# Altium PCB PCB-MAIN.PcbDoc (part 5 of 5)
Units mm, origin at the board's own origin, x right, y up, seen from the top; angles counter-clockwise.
Board outline 110 x 75 mm, 8 copper layers (F.Cu, In1.Cu, In2.Cu, In3.Cu, In4.Cu, In5.Cu, In6.Cu, B.Cu); 251 components, 185 nets, 1143 pads, 853 vias.
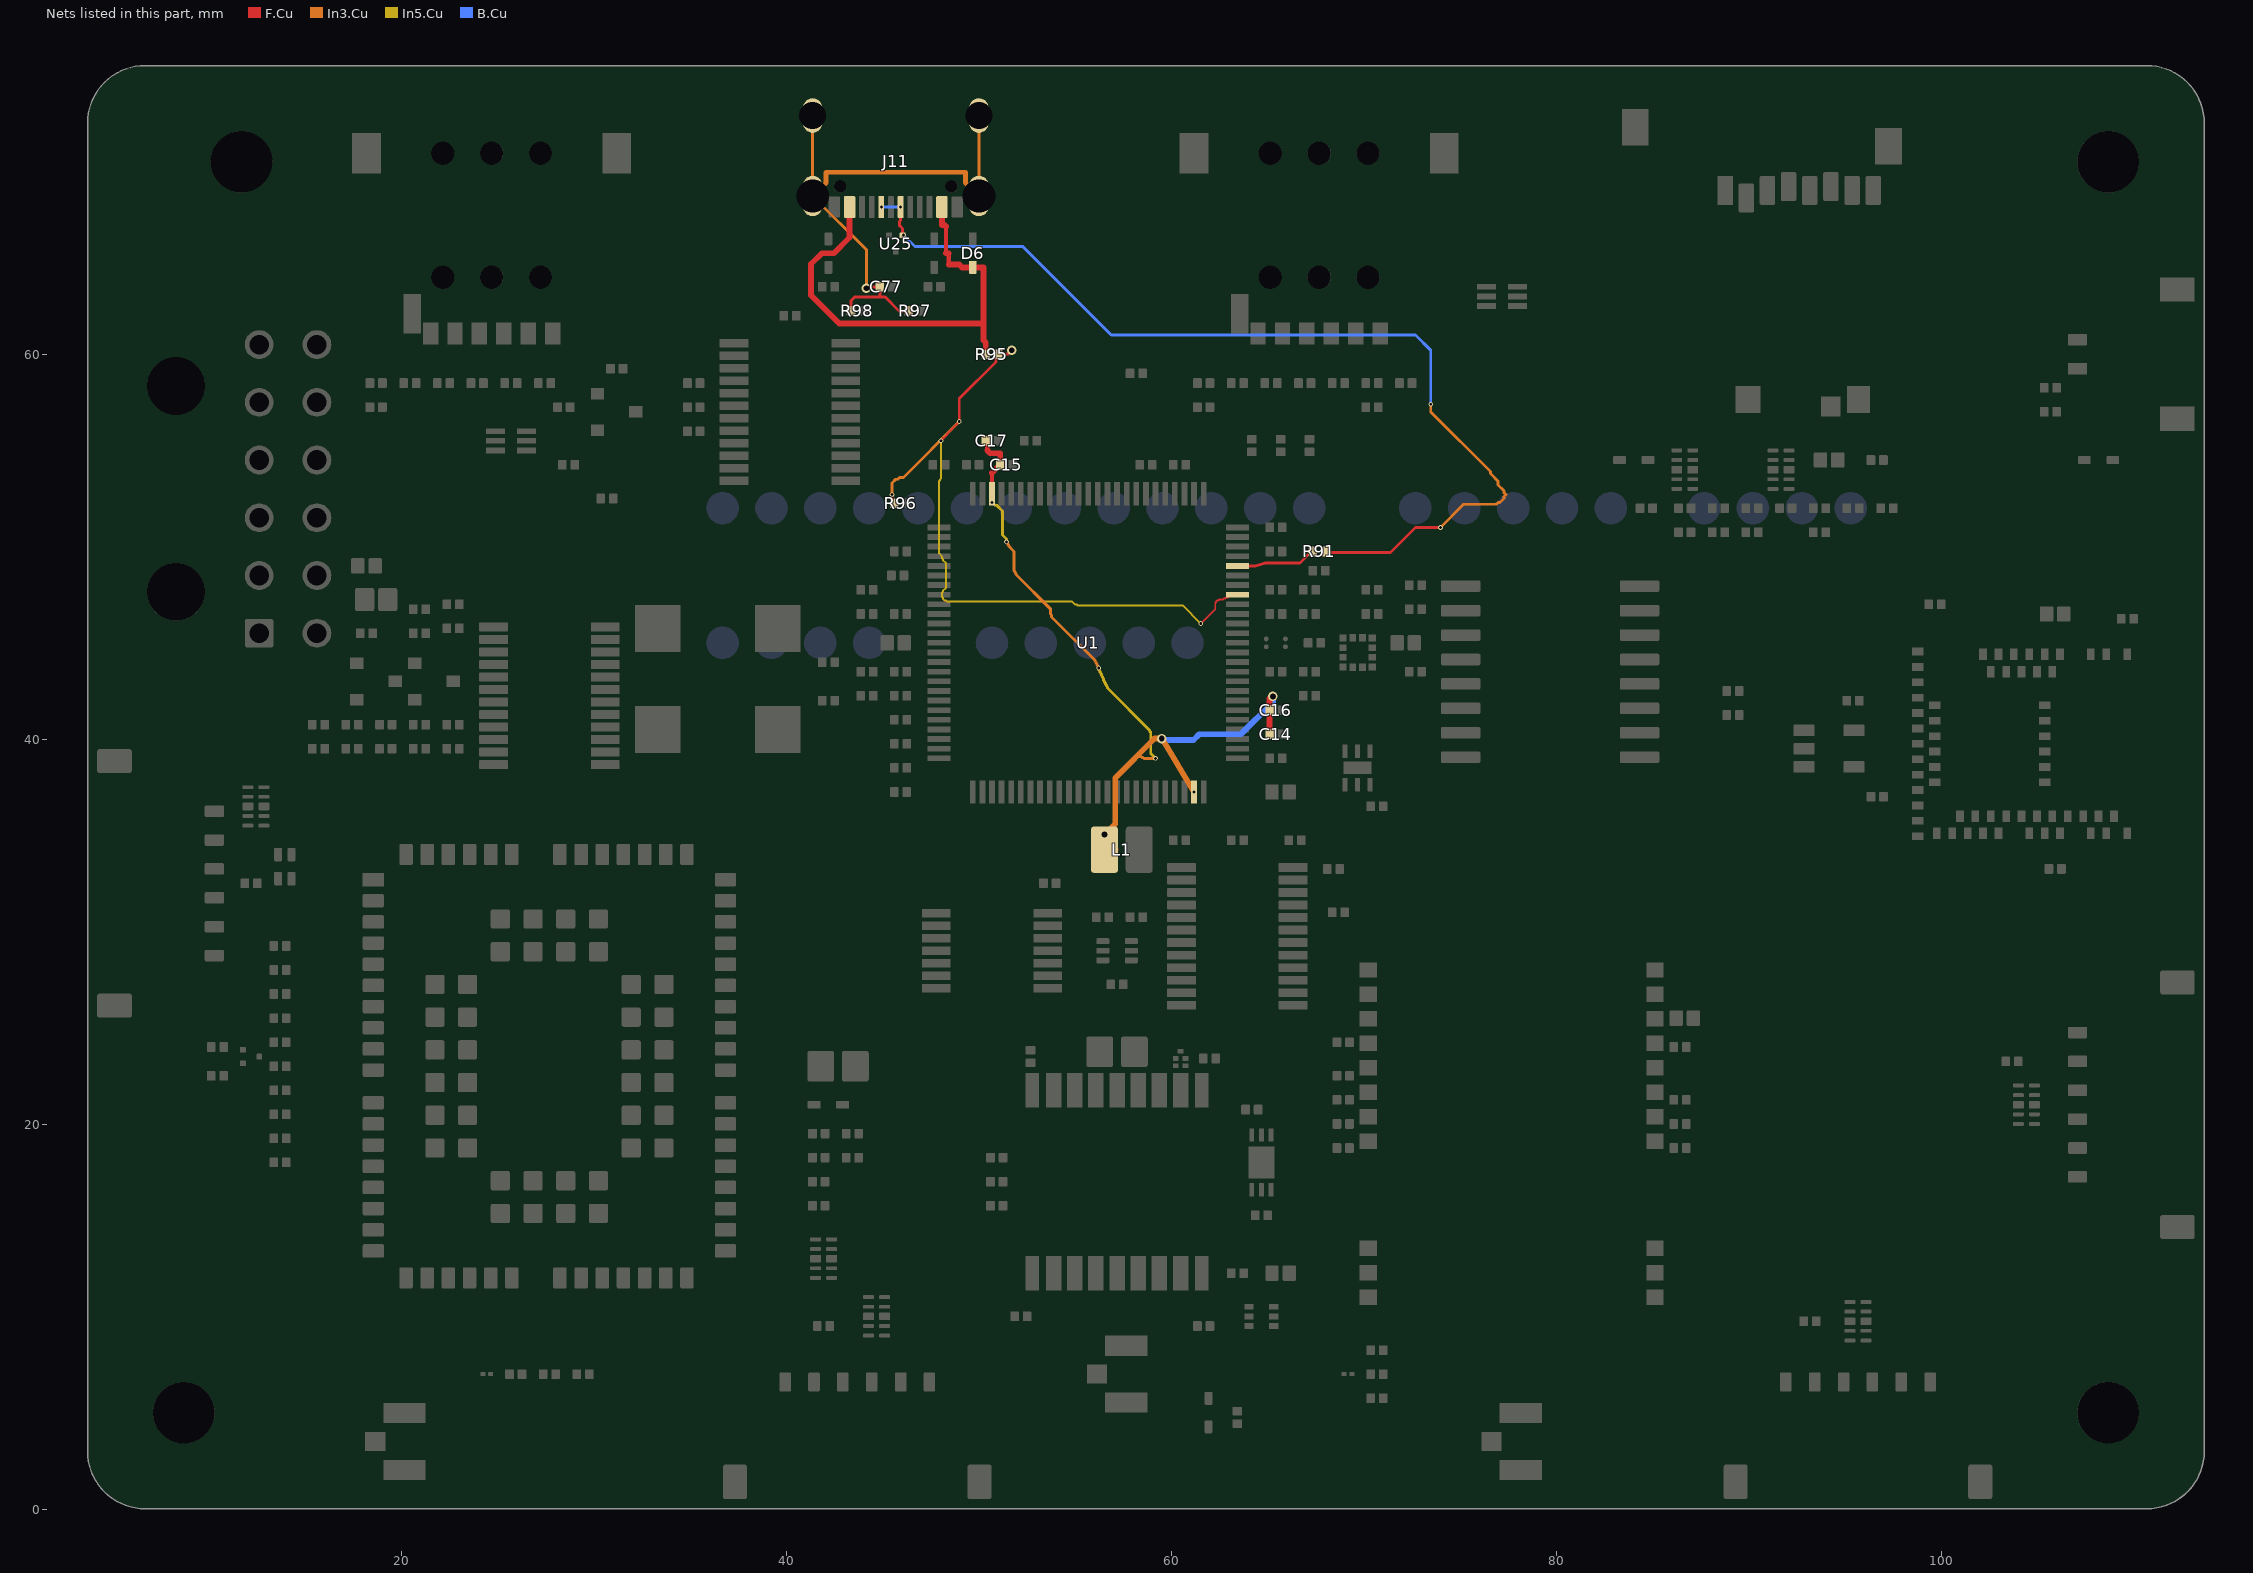
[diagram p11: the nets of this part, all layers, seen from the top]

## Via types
v1: diameter 0.5, hole 0.3, F.Cu to B.Cu, tented both sides, 579 vias
v2: diameter 0.25, hole 0.15, F.Cu to B.Cu, tented both sides, 274 vias

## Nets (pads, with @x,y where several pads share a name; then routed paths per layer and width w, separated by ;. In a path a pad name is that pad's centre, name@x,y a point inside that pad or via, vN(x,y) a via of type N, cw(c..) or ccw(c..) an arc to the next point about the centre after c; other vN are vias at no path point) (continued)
USB_DP_CONN: J11.A6 J11.B6 R91.2 U25.1 | length 52.2
  F.Cu w0.15: R91.2@68.085,49.725 71.385,49.725 72.685,51.025 v2(73.985,51.025)
  F.Cu w0.154: v2(45.935,67.67) 45.935,66.975 45.868,66.908 45.868,66.725 46.035,66.558 U25.1@46.035,66.2
  In3.Cu w0.15: v2(73.485,57.425) 73.485,57.025 76.585,53.925 76.585,53.825 76.985,53.425 76.985,53.225 77.285,52.925 77.285,52.825 77.385,52.725 77.285,52.625 77.285,52.525 77.085,52.325 76.985,52.325 76.885,52.225 75.185,52.225 v2(73.985,51.025)
  B.Cu w0.15: v2(46.085,66.225) 46.685,65.625 52.285,65.625 56.885,61.025 72.685,61.025 73.485,60.225 v2(73.485,57.425)
  B.Cu w0.154: v2(44.935,67.67) v2(45.935,67.67)
USB_DP_U1: R91.1 U1.71 | length 4.2
  F.Cu w0.154: U1.71@63.435,49.025 64.385,49.025 64.885,49.175 66.685,49.175 67.135,49.625 R91.1@67.36,49.775
USB_SHIELD: C77.1 J11.SHIELD R97.1 R98.1 | length 29.8
  F.Cu w0.15: R98.1@43.36,62.275 43.36,62.802 43.556,62.998 44.86,62.998 ; v1(44.159,63.449) 44.282,63.449 44.358,63.525 C77.1@44.86,63.525 44.86,62.998 ; R97.1@46.36,62.275 45.858,62.275 45.135,62.998 44.86,62.998
  In3.Cu w0.15: J11.SHIELD@41.365,72.425 J11.SHIELD@41.365,68.245 44.159,65.451 v1(44.159,63.449) ; J11.SHIELD@50.005,68.245 J11.SHIELD@50.005,72.425
  In3.Cu w0.25: J11.SHIELD@41.365,68.245 42.065,68.945 42.065,69.475 49.305,69.475 49.305,68.945 J11.SHIELD@50.005,68.245
USB_VBUS_CONN: D6.1 J11.A4 J11.A9 J11.B4 J11.B9 R95.1 | length 25.1
  F.Cu w0.225: 48.297,65.275 48.297,66.66 ; 48.435,64.683 48.435,65.275
  F.Cu w0.3: J11.B4@43.285,67.67 43.285,66.082 42.478,65.275 41.846,65.275 41.283,64.712 41.283,63.089 42.747,61.624 50.237,61.624 ; J11.B9@48.085,67.67 48.085,66.743 48.215,66.743 48.297,66.66 ; 48.297,65.275 48.435,65.275 ; 48.435,64.683 48.985,64.683 49.133,64.535 D6.1@49.685,64.535 50.237,64.535 50.237,61.624 ; R95.1@50.36,60.025 50.36,60.627 50.237,60.75 50.237,61.624
USB_VBUS_SENSE: R95.2 R96.1 U1.68 | length 37
  F.Cu w0.1: v2(48.035,55.525) 48.335,55.825 48.335,55.875 v2@48.935,56.475 ; v2(61.535,46.025) 62.285,46.775 62.285,47.075 62.335,47.125 62.335,47.175 62.385,47.225 62.435,47.225 62.485,47.275 62.685,47.275 62.735,47.325 62.785,47.325 62.835,47.375 62.935,47.375 U1.68@63.085,47.525
  F.Cu w0.15: v2(45.485,52.725) 45.485,52.525 45.585,52.425 R96.1@45.585,52.325 ; v2(48.985,56.525) 48.985,57.725 50.885,59.625 50.885,59.825 R95.2@50.985,59.925 ; R95.2@51.01,60.025 51.512,60.025 v1(51.712,60.225)
  In3.Cu w0.15: v2(45.485,52.725) 45.485,53.325 45.685,53.525 45.785,53.525 45.885,53.625 46.085,53.625 v2(48.985,56.525)
  In5.Cu w0.1: v2(48.035,55.525) 48.035,53.575 47.985,53.525 47.985,53.475 47.935,53.425 47.935,49.675 48.085,49.525 48.085,49.425 48.135,49.375 48.135,49.325 48.285,49.175 48.285,47.875 48.135,47.725 48.135,47.675 48.085,47.625 48.085,47.425 48.135,47.375 48.135,47.325 48.235,47.225 48.285,47.225 48.335,47.175 54.835,47.175 54.985,47.025 55.085,47.025 55.135,46.975 60.585,46.975 v2(61.535,46.025)
VCORE_1V1: C14.1 C15.1 C16.1 C17.1 L1.2 U1.49 U1.98 | length 41.4
  F.Cu w0.225: C17.1@50.36,55.525 50.434,55.451 50.434,55.028 ; U1.98@50.685,52.775 50.685,53.85
  F.Cu w0.3: 50.434,55.028 50.585,54.877 51.11,54.877 C15.1@51.11,54.275 50.685,53.85 ; v1(56.533,35.06) 56.533,34.275 L1.2@57.11,34.275 ; C14.1@65.11,40.275 C16.1@65.11,41.525 65.11,42.127 65.166,42.127 v1(65.281,42.242)
  In3.Cu w0.15: v2(51.435,50.275) 51.485,50.225 51.485,50.175 51.535,50.125 51.535,50.075 51.835,49.775 51.835,48.775 51.885,48.725 51.885,48.675 51.935,48.625 51.935,48.575 53.735,46.775 53.735,46.525 53.785,46.475 53.785,46.375 56.035,44.125 56.035,44.075 56.085,44.025 56.085,43.975 56.135,43.925 56.135,43.875 56.185,43.825 56.185,43.775 v2(56.235,43.725) ; 58.285,39.175 58.335,39.125 58.435,39.125 58.485,39.075 58.535,39.075 58.585,39.025 v2(59.185,39.025)
  In3.Cu w0.3: v1(56.533,35.06) 57.085,35.612 57.085,38.002 59.132,40.049 v1(59.509,40.049) v2(61.185,37.275)
  In5.Cu w0.15: v2(50.685,52.325) 50.835,52.175 50.935,52.175 51.235,51.875 51.235,50.625 51.435,50.425 v2(51.435,50.275) ; v2(56.235,43.725) 56.235,43.625 56.285,43.575 56.285,43.525 56.335,43.475 56.335,43.425 56.385,43.375 56.385,43.325 56.435,43.275 56.435,43.225 56.485,43.175 56.485,43.075 56.535,43.025 56.535,42.975 56.585,42.925 56.585,42.875 56.635,42.825 56.635,42.775 56.685,42.725 56.685,42.675 58.885,40.475 58.885,40.425 58.935,40.375 58.935,39.275 v2(59.185,39.025)
  B.Cu w0.3: v1(59.509,40.049) 59.583,39.974 61.16,39.974 61.457,40.272 63.613,40.272 65.281,41.94 v1(65.281,42.242)
pads on no net: D1.Un1 D1.Un2 D2.Un1 D2.Un2 H1.Un1 H2.Un1 H3.Un1 H4.Un1 J6.5 J6.Un1 J6.Un2 J6.Un3 J6.Un4 J6.Un5 J6.Un6 J7.5 J7.Un1 J7.Un2 J7.Un3 J7.Un4 J7.Un5 J7.Un6 J8.Un1 J8.Un2 J8.Un3 J9.Un1 J9.Un2 J9.Un3 J10.Un1 J10.Un2 J10.Un3 J11.A8 J11.B8 J11.Un1 J11.Un2 J13.Un1 J13.Un2 J_MIC1.Un1 J_MIC1.Un2 J_MIC2.Un1 J_MIC2.Un2 J_MIC3.Un1 J_MIC3.Un2 J_MIC4.Un1 J_MIC4.Un2 J_PWR.Un1 J_PWR.Un2 Q1.Un1 Q1.Un2 Q1.Un3 Q2.Un1 Q2.Un2 Q2.Un3 Q3.Un1 Q3.Un2 Q3.Un3 U1.9 U1.12 U1.13 U1.18 U1.23 U1.32 U1.36 U1.69 U1.84 U1.88 U1.89 U1.90 U1.91 U2.4 U2.5 U2.6 U2.11 U2.12 U2.13 U2.14 U3.5 U3.11 U4.2 U4.EP U6.1 U7.9 U7.10 U8.1 U8.2 U8.4 U8.5 U8.6 U8.7 U8.11 U8.12 U8.13 U8.14 U8.16 U8.18 U8.19 U8.21 U8.24 U8.25 U8.26 U8.27 U8.28 U8.36 U8.37 U8.38 U8.40 U8.41 U8.42 U8.49 U8.51 U8.56 U8.57 U8.63 U8.64 U8.65 U8.66 U8.76 U8.77 U8.78 U8.83 U8.84 U8.85 U8.86 U8.87 U8.88 U8.92 U8.93 U8.94 U8.95 U8.96 U8.97 U8.98 U8.99 U9.5 U9.6 U9.9 U9.15 U9.18 U10.8 U11.3 U11.4 U11.5 U11.6 U11.7 U11.8 U11.9 U11.10 U11.11 U11.12 U11.13 U11.14 U11.16 U11.17 U11.18 U11.19 U11.20 U11.21 U11.23 U11.25 U11.26 U11.27 U11.29 U11.31 U11.32 U11.34 U11.35 U11.36 U11.37 U11.38 U11.41 U11.42 U11.43 U11.44 U11.45 U11.46 U11.47 U11.48 U11.49 U11.50 U11.52 U11.54 U11.56 U11.57 U11.58 U11.59 U11.60 U11.61 U13.3 U16.9 U16.10 U16.18 U17.11 U19.6 U19.7 U19.9 U19.10 U19.Un1 U19.Un2 U20.6 U20.7 U20.9 U20.10 U20.Un1 U20.Un2 U21.6 U21.7 U21.9 U21.10 U21.Un1 U21.Un2 U22.6 U22.7 U22.9 U22.10 U22.Un1 U22.Un2 U23.6 U23.7 U23.9 U23.10 U23.Un1 U23.Un2 U24.5 U24.6 U24.7 U24.9 U24.10 U24.Un1 U24.Un2 U27.6 U27.7 U27.9 U27.10 U27.Un1 U27.Un2

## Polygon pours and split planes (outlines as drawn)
GND_MODEM on In1.Cu "In1.Cu-GND_MODEM" (solid, remove dead copper, pour order 8): 13.685,41.025 39.685,41.025 39.685,1.025 13.685,1.025
GND_DIGITAL on In1.Cu "In1.Cu-GND_DIGITAL" (solid, remove dead copper, pour order 5): 113.035,0.675 39.885,0.675 39.885,41.225 13.485,41.225 13.485,0.675 4.335,0.675 4.335,74.375 113.035,74.375
GND_MIC on In2.Cu "In2.Cu-GND_MIC" (solid, remove dead copper, pour order 9): 113.035,45.225 97.985,45.225 97.985,34.325 113.035,34.325 113.035,0.675 89.385,0.675 89.385,29.225 66.885,29.225 66.885,24.225 47.485,24.225 47.485,0.675 39.885,0.675 39.885,41.225 13.485,41.225 13.485,0.675 4.335,0.675 4.335,74.375 113.035,74.375
GND_DIGITAL on In4.Cu "In4.Cu-GND_DIGITAL" (solid, remove dead copper, pour order 10): 113.035,0.675 113.035,74.375 4.335,74.375 4.335,0.675 13.485,0.675 13.485,41.225 39.885,41.225 39.885,0.675
GND_MODEM on In4.Cu "In4.Cu-GND_MODEM-1" (solid, remove dead copper, pour order 7): 299 vertices, not listed, extent 8.612,0.675 79.488,72.125
GND_MODEM on In4.Cu "In4.Cu-GND_MODEM" (solid, remove dead copper, pour order 6): 59.694,45.365 59.645,45.042 59.665,44.808 59.73,44.582 59.838,44.373 59.985,44.189 60.164,44.037 60.37,43.923 60.594,43.852 60.828,43.825 61.062,43.845 61.288,43.91 61.497,44.018 61.681,44.165 61.833,44.344 61.947,44.55 62.018,44.774 62.045,45.042 61.988,45.39 61.849,45.681 61.619,45.941 61.395,46.091 61.062,46.205 60.744,46.221 60.461,46.161 60.304,46.378 60.044,46.51 59.81,46.516 59.591,46.433 59.424,46.276 59.331,46.083 59.312,45.883 59.363,45.68 59.498,45.489
GND_DIGITAL on In6.Cu "In6.Cu-GND_DIGITAL" (solid, remove dead copper, pour order 11): 113.035,0.675 113.035,74.375 4.335,74.375 4.335,0.675 13.485,0.675 13.485,41.225 39.885,41.225 39.885,0.675

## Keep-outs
F.Cu:
  region: 109.88,45.034 109.88,34.519 113.69,34.519 113.69,45.034
  region: 108.661,42.088 108.661,40.462 109.906,40.462 109.906,42.088
  region: 9.078,9.016 9.467,8.958 9.849,8.862 10.22,8.73 10.575,8.562 10.913,8.359 11.229,8.125 11.52,7.86 11.785,7.569 12.019,7.253 12.222,6.915 12.39,6.56 12.522,6.189 12.618,5.807 12.676,5.418 12.695,5.025 12.676,4.632 12.618,4.243 12.522,3.861 12.39,3.49 12.222,3.135 12.019,2.797 11.785,2.481 11.52,2.19 11.229,1.925 10.913,1.691 10.575,1.488 10.22,1.32 9.849,1.188 9.467,1.092 9.078,1.034 8.685,1.015 8.292,1.034 7.903,1.092 7.521,1.188 7.15,1.32 6.795,1.488 6.457,1.691 6.141,1.925 5.85,2.19 5.585,2.481 5.351,2.797 5.148,3.135 4.98,3.49 4.848,3.861 4.752,4.243 4.694,4.632 4.675,5.025 4.694,5.418 4.752,5.807 4.848,6.189 4.98,6.56 5.148,6.915 5.351,7.253 5.585,7.569 5.85,7.86 6.141,8.125 6.457,8.359 6.795,8.562 7.15,8.73 7.521,8.862 7.903,8.958 8.292,9.016 8.685,9.035
  region: 109.078,9.016 109.467,8.958 109.849,8.862 110.22,8.73 110.575,8.562 110.913,8.359 111.229,8.125 111.52,7.86 111.785,7.569 112.019,7.253 112.222,6.915 112.39,6.56 112.522,6.189 112.618,5.807 112.676,5.418 112.695,5.025 112.676,4.632 112.618,4.243 112.522,3.861 112.39,3.49 112.222,3.135 112.019,2.797 111.785,2.481 111.52,2.19 111.229,1.925 110.913,1.691 110.575,1.488 110.22,1.32 109.849,1.188 109.467,1.092 109.078,1.034 108.685,1.015 108.292,1.034 107.903,1.092 107.521,1.188 107.15,1.32 106.795,1.488 106.457,1.691 106.141,1.925 105.849,2.19 105.585,2.481 105.351,2.797 105.148,3.135 104.98,3.49 104.848,3.861 104.752,4.243 104.694,4.632 104.675,5.025 104.694,5.418 104.752,5.807 104.848,6.189 104.98,6.56 105.148,6.915 105.351,7.253 105.585,7.569 105.849,7.86 106.141,8.125 106.457,8.359 106.795,8.562 107.15,8.73 107.521,8.862 107.903,8.958 108.292,9.016 108.685,9.035
  region: 109.078,74.016 109.467,73.958 109.849,73.862 110.22,73.73 110.575,73.562 110.913,73.359 111.229,73.125 111.52,72.86 111.785,72.569 112.019,72.253 112.222,71.915 112.39,71.56 112.522,71.189 112.618,70.807 112.676,70.418 112.695,70.025 112.676,69.632 112.618,69.243 112.522,68.861 112.39,68.49 112.222,68.135 112.019,67.797 111.785,67.481 111.52,67.19 111.229,66.925 110.913,66.691 110.575,66.488 110.22,66.32 109.849,66.188 109.467,66.092 109.078,66.034 108.685,66.015 108.292,66.034 107.903,66.092 107.521,66.188 107.15,66.32 106.795,66.488 106.457,66.691 106.141,66.925 105.849,67.19 105.585,67.481 105.351,67.797 105.148,68.135 104.98,68.49 104.848,68.861 104.752,69.243 104.694,69.632 104.675,70.025 104.694,70.418 104.752,70.807 104.848,71.189 104.98,71.56 105.148,71.915 105.351,72.253 105.585,72.569 105.849,72.86 106.141,73.125 106.457,73.359 106.795,73.562 107.15,73.73 107.521,73.862 107.903,73.958 108.292,74.016 108.685,74.035
  region: 12.078,74.016 12.467,73.958 12.849,73.862 13.22,73.73 13.575,73.562 13.913,73.359 14.229,73.125 14.52,72.86 14.785,72.569 15.019,72.253 15.222,71.915 15.39,71.56 15.522,71.189 15.618,70.807 15.676,70.418 15.695,70.025 15.676,69.632 15.618,69.243 15.522,68.861 15.39,68.49 15.222,68.135 15.019,67.797 14.785,67.481 14.52,67.19 14.229,66.925 13.913,66.691 13.575,66.488 13.22,66.32 12.849,66.188 12.467,66.092 12.078,66.034 11.685,66.015 11.292,66.034 10.903,66.092 10.521,66.188 10.15,66.32 9.795,66.488 9.457,66.691 9.141,66.925 8.849,67.19 8.585,67.481 8.351,67.797 8.148,68.135 7.98,68.49 7.848,68.861 7.752,69.243 7.694,69.632 7.675,70.025 7.694,70.418 7.752,70.807 7.848,71.189 7.98,71.56 8.148,71.915 8.351,72.253 8.585,72.569 8.849,72.86 9.141,73.125 9.457,73.359 9.795,73.562 10.15,73.73 10.521,73.862 10.903,73.958 11.292,74.016 11.685,74.035
In1.Cu:
  region: 109.88,45.034 109.88,34.519 113.69,34.519 113.69,45.034
  region: 9.078,9.016 9.467,8.958 9.849,8.862 10.22,8.73 10.575,8.562 10.913,8.359 11.229,8.125 11.52,7.86 11.785,7.569 12.019,7.253 12.222,6.915 12.39,6.56 12.522,6.189 12.618,5.807 12.676,5.418 12.695,5.025 12.676,4.632 12.618,4.243 12.522,3.861 12.39,3.49 12.222,3.135 12.019,2.797 11.785,2.481 11.52,2.19 11.229,1.925 10.913,1.691 10.575,1.488 10.22,1.32 9.849,1.188 9.467,1.092 9.078,1.034 8.685,1.015 8.292,1.034 7.903,1.092 7.521,1.188 7.15,1.32 6.795,1.488 6.457,1.691 6.141,1.925 5.85,2.19 5.585,2.481 5.351,2.797 5.148,3.135 4.98,3.49 4.848,3.861 4.752,4.243 4.694,4.632 4.675,5.025 4.694,5.418 4.752,5.807 4.848,6.189 4.98,6.56 5.148,6.915 5.351,7.253 5.585,7.569 5.85,7.86 6.141,8.125 6.457,8.359 6.795,8.562 7.15,8.73 7.521,8.862 7.903,8.958 8.292,9.016 8.685,9.035
  region: 109.078,9.016 109.467,8.958 109.849,8.862 110.22,8.73 110.575,8.562 110.913,8.359 111.229,8.125 111.52,7.86 111.785,7.569 112.019,7.253 112.222,6.915 112.39,6.56 112.522,6.189 112.618,5.807 112.676,5.418 112.695,5.025 112.676,4.632 112.618,4.243 112.522,3.861 112.39,3.49 112.222,3.135 112.019,2.797 111.785,2.481 111.52,2.19 111.229,1.925 110.913,1.691 110.575,1.488 110.22,1.32 109.849,1.188 109.467,1.092 109.078,1.034 108.685,1.015 108.292,1.034 107.903,1.092 107.521,1.188 107.15,1.32 106.795,1.488 106.457,1.691 106.141,1.925 105.849,2.19 105.585,2.481 105.351,2.797 105.148,3.135 104.98,3.49 104.848,3.861 104.752,4.243 104.694,4.632 104.675,5.025 104.694,5.418 104.752,5.807 104.848,6.189 104.98,6.56 105.148,6.915 105.351,7.253 105.585,7.569 105.849,7.86 106.141,8.125 106.457,8.359 106.795,8.562 107.15,8.73 107.521,8.862 107.903,8.958 108.292,9.016 108.685,9.035
  region: 109.078,74.016 109.467,73.958 109.849,73.862 110.22,73.73 110.575,73.562 110.913,73.359 111.229,73.125 111.52,72.86 111.785,72.569 112.019,72.253 112.222,71.915 112.39,71.56 112.522,71.189 112.618,70.807 112.676,70.418 112.695,70.025 112.676,69.632 112.618,69.243 112.522,68.861 112.39,68.49 112.222,68.135 112.019,67.797 111.785,67.481 111.52,67.19 111.229,66.925 110.913,66.691 110.575,66.488 110.22,66.32 109.849,66.188 109.467,66.092 109.078,66.034 108.685,66.015 108.292,66.034 107.903,66.092 107.521,66.188 107.15,66.32 106.795,66.488 106.457,66.691 106.141,66.925 105.849,67.19 105.585,67.481 105.351,67.797 105.148,68.135 104.98,68.49 104.848,68.861 104.752,69.243 104.694,69.632 104.675,70.025 104.694,70.418 104.752,70.807 104.848,71.189 104.98,71.56 105.148,71.915 105.351,72.253 105.585,72.569 105.849,72.86 106.141,73.125 106.457,73.359 106.795,73.562 107.15,73.73 107.521,73.862 107.903,73.958 108.292,74.016 108.685,74.035
  region: 12.078,74.016 12.467,73.958 12.849,73.862 13.22,73.73 13.575,73.562 13.913,73.359 14.229,73.125 14.52,72.86 14.785,72.569 15.019,72.253 15.222,71.915 15.39,71.56 15.522,71.189 15.618,70.807 15.676,70.418 15.695,70.025 15.676,69.632 15.618,69.243 15.522,68.861 15.39,68.49 15.222,68.135 15.019,67.797 14.785,67.481 14.52,67.19 14.229,66.925 13.913,66.691 13.575,66.488 13.22,66.32 12.849,66.188 12.467,66.092 12.078,66.034 11.685,66.015 11.292,66.034 10.903,66.092 10.521,66.188 10.15,66.32 9.795,66.488 9.457,66.691 9.141,66.925 8.849,67.19 8.585,67.481 8.351,67.797 8.148,68.135 7.98,68.49 7.848,68.861 7.752,69.243 7.694,69.632 7.675,70.025 7.694,70.418 7.752,70.807 7.848,71.189 7.98,71.56 8.148,71.915 8.351,72.253 8.585,72.569 8.849,72.86 9.141,73.125 9.457,73.359 9.795,73.562 10.15,73.73 10.521,73.862 10.903,73.958 11.292,74.016 11.685,74.035
In2.Cu:
  region: 109.88,45.034 109.88,34.519 113.69,34.519 113.69,45.034
  region: 9.078,9.016 9.467,8.958 9.849,8.862 10.22,8.73 10.575,8.562 10.913,8.359 11.229,8.125 11.52,7.86 11.785,7.569 12.019,7.253 12.222,6.915 12.39,6.56 12.522,6.189 12.618,5.807 12.676,5.418 12.695,5.025 12.676,4.632 12.618,4.243 12.522,3.861 12.39,3.49 12.222,3.135 12.019,2.797 11.785,2.481 11.52,2.19 11.229,1.925 10.913,1.691 10.575,1.488 10.22,1.32 9.849,1.188 9.467,1.092 9.078,1.034 8.685,1.015 8.292,1.034 7.903,1.092 7.521,1.188 7.15,1.32 6.795,1.488 6.457,1.691 6.141,1.925 5.85,2.19 5.585,2.481 5.351,2.797 5.148,3.135 4.98,3.49 4.848,3.861 4.752,4.243 4.694,4.632 4.675,5.025 4.694,5.418 4.752,5.807 4.848,6.189 4.98,6.56 5.148,6.915 5.351,7.253 5.585,7.569 5.85,7.86 6.141,8.125 6.457,8.359 6.795,8.562 7.15,8.73 7.521,8.862 7.903,8.958 8.292,9.016 8.685,9.035
  region: 109.078,9.016 109.467,8.958 109.849,8.862 110.22,8.73 110.575,8.562 110.913,8.359 111.229,8.125 111.52,7.86 111.785,7.569 112.019,7.253 112.222,6.915 112.39,6.56 112.522,6.189 112.618,5.807 112.676,5.418 112.695,5.025 112.676,4.632 112.618,4.243 112.522,3.861 112.39,3.49 112.222,3.135 112.019,2.797 111.785,2.481 111.52,2.19 111.229,1.925 110.913,1.691 110.575,1.488 110.22,1.32 109.849,1.188 109.467,1.092 109.078,1.034 108.685,1.015 108.292,1.034 107.903,1.092 107.521,1.188 107.15,1.32 106.795,1.488 106.457,1.691 106.141,1.925 105.849,2.19 105.585,2.481 105.351,2.797 105.148,3.135 104.98,3.49 104.848,3.861 104.752,4.243 104.694,4.632 104.675,5.025 104.694,5.418 104.752,5.807 104.848,6.189 104.98,6.56 105.148,6.915 105.351,7.253 105.585,7.569 105.849,7.86 106.141,8.125 106.457,8.359 106.795,8.562 107.15,8.73 107.521,8.862 107.903,8.958 108.292,9.016 108.685,9.035
  region: 109.078,74.016 109.467,73.958 109.849,73.862 110.22,73.73 110.575,73.562 110.913,73.359 111.229,73.125 111.52,72.86 111.785,72.569 112.019,72.253 112.222,71.915 112.39,71.56 112.522,71.189 112.618,70.807 112.676,70.418 112.695,70.025 112.676,69.632 112.618,69.243 112.522,68.861 112.39,68.49 112.222,68.135 112.019,67.797 111.785,67.481 111.52,67.19 111.229,66.925 110.913,66.691 110.575,66.488 110.22,66.32 109.849,66.188 109.467,66.092 109.078,66.034 108.685,66.015 108.292,66.034 107.903,66.092 107.521,66.188 107.15,66.32 106.795,66.488 106.457,66.691 106.141,66.925 105.849,67.19 105.585,67.481 105.351,67.797 105.148,68.135 104.98,68.49 104.848,68.861 104.752,69.243 104.694,69.632 104.675,70.025 104.694,70.418 104.752,70.807 104.848,71.189 104.98,71.56 105.148,71.915 105.351,72.253 105.585,72.569 105.849,72.86 106.141,73.125 106.457,73.359 106.795,73.562 107.15,73.73 107.521,73.862 107.903,73.958 108.292,74.016 108.685,74.035
  region: 12.078,74.016 12.467,73.958 12.849,73.862 13.22,73.73 13.575,73.562 13.913,73.359 14.229,73.125 14.52,72.86 14.785,72.569 15.019,72.253 15.222,71.915 15.39,71.56 15.522,71.189 15.618,70.807 15.676,70.418 15.695,70.025 15.676,69.632 15.618,69.243 15.522,68.861 15.39,68.49 15.222,68.135 15.019,67.797 14.785,67.481 14.52,67.19 14.229,66.925 13.913,66.691 13.575,66.488 13.22,66.32 12.849,66.188 12.467,66.092 12.078,66.034 11.685,66.015 11.292,66.034 10.903,66.092 10.521,66.188 10.15,66.32 9.795,66.488 9.457,66.691 9.141,66.925 8.849,67.19 8.585,67.481 8.351,67.797 8.148,68.135 7.98,68.49 7.848,68.861 7.752,69.243 7.694,69.632 7.675,70.025 7.694,70.418 7.752,70.807 7.848,71.189 7.98,71.56 8.148,71.915 8.351,72.253 8.585,72.569 8.849,72.86 9.141,73.125 9.457,73.359 9.795,73.562 10.15,73.73 10.521,73.862 10.903,73.958 11.292,74.016 11.685,74.035
In3.Cu:
  region: 109.88,45.034 109.88,34.519 113.69,34.519 113.69,45.034
  region: 9.078,9.016 9.467,8.958 9.849,8.862 10.22,8.73 10.575,8.562 10.913,8.359 11.229,8.125 11.52,7.86 11.785,7.569 12.019,7.253 12.222,6.915 12.39,6.56 12.522,6.189 12.618,5.807 12.676,5.418 12.695,5.025 12.676,4.632 12.618,4.243 12.522,3.861 12.39,3.49 12.222,3.135 12.019,2.797 11.785,2.481 11.52,2.19 11.229,1.925 10.913,1.691 10.575,1.488 10.22,1.32 9.849,1.188 9.467,1.092 9.078,1.034 8.685,1.015 8.292,1.034 7.903,1.092 7.521,1.188 7.15,1.32 6.795,1.488 6.457,1.691 6.141,1.925 5.85,2.19 5.585,2.481 5.351,2.797 5.148,3.135 4.98,3.49 4.848,3.861 4.752,4.243 4.694,4.632 4.675,5.025 4.694,5.418 4.752,5.807 4.848,6.189 4.98,6.56 5.148,6.915 5.351,7.253 5.585,7.569 5.85,7.86 6.141,8.125 6.457,8.359 6.795,8.562 7.15,8.73 7.521,8.862 7.903,8.958 8.292,9.016 8.685,9.035
  region: 109.078,9.016 109.467,8.958 109.849,8.862 110.22,8.73 110.575,8.562 110.913,8.359 111.229,8.125 111.52,7.86 111.785,7.569 112.019,7.253 112.222,6.915 112.39,6.56 112.522,6.189 112.618,5.807 112.676,5.418 112.695,5.025 112.676,4.632 112.618,4.243 112.522,3.861 112.39,3.49 112.222,3.135 112.019,2.797 111.785,2.481 111.52,2.19 111.229,1.925 110.913,1.691 110.575,1.488 110.22,1.32 109.849,1.188 109.467,1.092 109.078,1.034 108.685,1.015 108.292,1.034 107.903,1.092 107.521,1.188 107.15,1.32 106.795,1.488 106.457,1.691 106.141,1.925 105.849,2.19 105.585,2.481 105.351,2.797 105.148,3.135 104.98,3.49 104.848,3.861 104.752,4.243 104.694,4.632 104.675,5.025 104.694,5.418 104.752,5.807 104.848,6.189 104.98,6.56 105.148,6.915 105.351,7.253 105.585,7.569 105.849,7.86 106.141,8.125 106.457,8.359 106.795,8.562 107.15,8.73 107.521,8.862 107.903,8.958 108.292,9.016 108.685,9.035
  region: 109.078,74.016 109.467,73.958 109.849,73.862 110.22,73.73 110.575,73.562 110.913,73.359 111.229,73.125 111.52,72.86 111.785,72.569 112.019,72.253 112.222,71.915 112.39,71.56 112.522,71.189 112.618,70.807 112.676,70.418 112.695,70.025 112.676,69.632 112.618,69.243 112.522,68.861 112.39,68.49 112.222,68.135 112.019,67.797 111.785,67.481 111.52,67.19 111.229,66.925 110.913,66.691 110.575,66.488 110.22,66.32 109.849,66.188 109.467,66.092 109.078,66.034 108.685,66.015 108.292,66.034 107.903,66.092 107.521,66.188 107.15,66.32 106.795,66.488 106.457,66.691 106.141,66.925 105.849,67.19 105.585,67.481 105.351,67.797 105.148,68.135 104.98,68.49 104.848,68.861 104.752,69.243 104.694,69.632 104.675,70.025 104.694,70.418 104.752,70.807 104.848,71.189 104.98,71.56 105.148,71.915 105.351,72.253 105.585,72.569 105.849,72.86 106.141,73.125 106.457,73.359 106.795,73.562 107.15,73.73 107.521,73.862 107.903,73.958 108.292,74.016 108.685,74.035
  region: 12.078,74.016 12.467,73.958 12.849,73.862 13.22,73.73 13.575,73.562 13.913,73.359 14.229,73.125 14.52,72.86 14.785,72.569 15.019,72.253 15.222,71.915 15.39,71.56 15.522,71.189 15.618,70.807 15.676,70.418 15.695,70.025 15.676,69.632 15.618,69.243 15.522,68.861 15.39,68.49 15.222,68.135 15.019,67.797 14.785,67.481 14.52,67.19 14.229,66.925 13.913,66.691 13.575,66.488 13.22,66.32 12.849,66.188 12.467,66.092 12.078,66.034 11.685,66.015 11.292,66.034 10.903,66.092 10.521,66.188 10.15,66.32 9.795,66.488 9.457,66.691 9.141,66.925 8.849,67.19 8.585,67.481 8.351,67.797 8.148,68.135 7.98,68.49 7.848,68.861 7.752,69.243 7.694,69.632 7.675,70.025 7.694,70.418 7.752,70.807 7.848,71.189 7.98,71.56 8.148,71.915 8.351,72.253 8.585,72.569 8.849,72.86 9.141,73.125 9.457,73.359 9.795,73.562 10.15,73.73 10.521,73.862 10.903,73.958 11.292,74.016 11.685,74.035
In4.Cu:
  region: 109.88,45.034 109.88,34.519 113.69,34.519 113.69,45.034
  region: 9.078,9.016 9.467,8.958 9.849,8.862 10.22,8.73 10.575,8.562 10.913,8.359 11.229,8.125 11.52,7.86 11.785,7.569 12.019,7.253 12.222,6.915 12.39,6.56 12.522,6.189 12.618,5.807 12.676,5.418 12.695,5.025 12.676,4.632 12.618,4.243 12.522,3.861 12.39,3.49 12.222,3.135 12.019,2.797 11.785,2.481 11.52,2.19 11.229,1.925 10.913,1.691 10.575,1.488 10.22,1.32 9.849,1.188 9.467,1.092 9.078,1.034 8.685,1.015 8.292,1.034 7.903,1.092 7.521,1.188 7.15,1.32 6.795,1.488 6.457,1.691 6.141,1.925 5.85,2.19 5.585,2.481 5.351,2.797 5.148,3.135 4.98,3.49 4.848,3.861 4.752,4.243 4.694,4.632 4.675,5.025 4.694,5.418 4.752,5.807 4.848,6.189 4.98,6.56 5.148,6.915 5.351,7.253 5.585,7.569 5.85,7.86 6.141,8.125 6.457,8.359 6.795,8.562 7.15,8.73 7.521,8.862 7.903,8.958 8.292,9.016 8.685,9.035
  region: 109.078,9.016 109.467,8.958 109.849,8.862 110.22,8.73 110.575,8.562 110.913,8.359 111.229,8.125 111.52,7.86 111.785,7.569 112.019,7.253 112.222,6.915 112.39,6.56 112.522,6.189 112.618,5.807 112.676,5.418 112.695,5.025 112.676,4.632 112.618,4.243 112.522,3.861 112.39,3.49 112.222,3.135 112.019,2.797 111.785,2.481 111.52,2.19 111.229,1.925 110.913,1.691 110.575,1.488 110.22,1.32 109.849,1.188 109.467,1.092 109.078,1.034 108.685,1.015 108.292,1.034 107.903,1.092 107.521,1.188 107.15,1.32 106.795,1.488 106.457,1.691 106.141,1.925 105.849,2.19 105.585,2.481 105.351,2.797 105.148,3.135 104.98,3.49 104.848,3.861 104.752,4.243 104.694,4.632 104.675,5.025 104.694,5.418 104.752,5.807 104.848,6.189 104.98,6.56 105.148,6.915 105.351,7.253 105.585,7.569 105.849,7.86 106.141,8.125 106.457,8.359 106.795,8.562 107.15,8.73 107.521,8.862 107.903,8.958 108.292,9.016 108.685,9.035
  region: 109.078,74.016 109.467,73.958 109.849,73.862 110.22,73.73 110.575,73.562 110.913,73.359 111.229,73.125 111.52,72.86 111.785,72.569 112.019,72.253 112.222,71.915 112.39,71.56 112.522,71.189 112.618,70.807 112.676,70.418 112.695,70.025 112.676,69.632 112.618,69.243 112.522,68.861 112.39,68.49 112.222,68.135 112.019,67.797 111.785,67.481 111.52,67.19 111.229,66.925 110.913,66.691 110.575,66.488 110.22,66.32 109.849,66.188 109.467,66.092 109.078,66.034 108.685,66.015 108.292,66.034 107.903,66.092 107.521,66.188 107.15,66.32 106.795,66.488 106.457,66.691 106.141,66.925 105.849,67.19 105.585,67.481 105.351,67.797 105.148,68.135 104.98,68.49 104.848,68.861 104.752,69.243 104.694,69.632 104.675,70.025 104.694,70.418 104.752,70.807 104.848,71.189 104.98,71.56 105.148,71.915 105.351,72.253 105.585,72.569 105.849,72.86 106.141,73.125 106.457,73.359 106.795,73.562 107.15,73.73 107.521,73.862 107.903,73.958 108.292,74.016 108.685,74.035
  region: 12.078,74.016 12.467,73.958 12.849,73.862 13.22,73.73 13.575,73.562 13.913,73.359 14.229,73.125 14.52,72.86 14.785,72.569 15.019,72.253 15.222,71.915 15.39,71.56 15.522,71.189 15.618,70.807 15.676,70.418 15.695,70.025 15.676,69.632 15.618,69.243 15.522,68.861 15.39,68.49 15.222,68.135 15.019,67.797 14.785,67.481 14.52,67.19 14.229,66.925 13.913,66.691 13.575,66.488 13.22,66.32 12.849,66.188 12.467,66.092 12.078,66.034 11.685,66.015 11.292,66.034 10.903,66.092 10.521,66.188 10.15,66.32 9.795,66.488 9.457,66.691 9.141,66.925 8.849,67.19 8.585,67.481 8.351,67.797 8.148,68.135 7.98,68.49 7.848,68.861 7.752,69.243 7.694,69.632 7.675,70.025 7.694,70.418 7.752,70.807 7.848,71.189 7.98,71.56 8.148,71.915 8.351,72.253 8.585,72.569 8.849,72.86 9.141,73.125 9.457,73.359 9.795,73.562 10.15,73.73 10.521,73.862 10.903,73.958 11.292,74.016 11.685,74.035
In5.Cu:
  region: 109.88,45.034 109.88,34.519 113.69,34.519 113.69,45.034
  region: 9.078,9.016 9.467,8.958 9.849,8.862 10.22,8.73 10.575,8.562 10.913,8.359 11.229,8.125 11.52,7.86 11.785,7.569 12.019,7.253 12.222,6.915 12.39,6.56 12.522,6.189 12.618,5.807 12.676,5.418 12.695,5.025 12.676,4.632 12.618,4.243 12.522,3.861 12.39,3.49 12.222,3.135 12.019,2.797 11.785,2.481 11.52,2.19 11.229,1.925 10.913,1.691 10.575,1.488 10.22,1.32 9.849,1.188 9.467,1.092 9.078,1.034 8.685,1.015 8.292,1.034 7.903,1.092 7.521,1.188 7.15,1.32 6.795,1.488 6.457,1.691 6.141,1.925 5.85,2.19 5.585,2.481 5.351,2.797 5.148,3.135 4.98,3.49 4.848,3.861 4.752,4.243 4.694,4.632 4.675,5.025 4.694,5.418 4.752,5.807 4.848,6.189 4.98,6.56 5.148,6.915 5.351,7.253 5.585,7.569 5.85,7.86 6.141,8.125 6.457,8.359 6.795,8.562 7.15,8.73 7.521,8.862 7.903,8.958 8.292,9.016 8.685,9.035
  region: 109.078,9.016 109.467,8.958 109.849,8.862 110.22,8.73 110.575,8.562 110.913,8.359 111.229,8.125 111.52,7.86 111.785,7.569 112.019,7.253 112.222,6.915 112.39,6.56 112.522,6.189 112.618,5.807 112.676,5.418 112.695,5.025 112.676,4.632 112.618,4.243 112.522,3.861 112.39,3.49 112.222,3.135 112.019,2.797 111.785,2.481 111.52,2.19 111.229,1.925 110.913,1.691 110.575,1.488 110.22,1.32 109.849,1.188 109.467,1.092 109.078,1.034 108.685,1.015 108.292,1.034 107.903,1.092 107.521,1.188 107.15,1.32 106.795,1.488 106.457,1.691 106.141,1.925 105.849,2.19 105.585,2.481 105.351,2.797 105.148,3.135 104.98,3.49 104.848,3.861 104.752,4.243 104.694,4.632 104.675,5.025 104.694,5.418 104.752,5.807 104.848,6.189 104.98,6.56 105.148,6.915 105.351,7.253 105.585,7.569 105.849,7.86 106.141,8.125 106.457,8.359 106.795,8.562 107.15,8.73 107.521,8.862 107.903,8.958 108.292,9.016 108.685,9.035
  region: 109.078,74.016 109.467,73.958 109.849,73.862 110.22,73.73 110.575,73.562 110.913,73.359 111.229,73.125 111.52,72.86 111.785,72.569 112.019,72.253 112.222,71.915 112.39,71.56 112.522,71.189 112.618,70.807 112.676,70.418 112.695,70.025 112.676,69.632 112.618,69.243 112.522,68.861 112.39,68.49 112.222,68.135 112.019,67.797 111.785,67.481 111.52,67.19 111.229,66.925 110.913,66.691 110.575,66.488 110.22,66.32 109.849,66.188 109.467,66.092 109.078,66.034 108.685,66.015 108.292,66.034 107.903,66.092 107.521,66.188 107.15,66.32 106.795,66.488 106.457,66.691 106.141,66.925 105.849,67.19 105.585,67.481 105.351,67.797 105.148,68.135 104.98,68.49 104.848,68.861 104.752,69.243 104.694,69.632 104.675,70.025 104.694,70.418 104.752,70.807 104.848,71.189 104.98,71.56 105.148,71.915 105.351,72.253 105.585,72.569 105.849,72.86 106.141,73.125 106.457,73.359 106.795,73.562 107.15,73.73 107.521,73.862 107.903,73.958 108.292,74.016 108.685,74.035
  region: 12.078,74.016 12.467,73.958 12.849,73.862 13.22,73.73 13.575,73.562 13.913,73.359 14.229,73.125 14.52,72.86 14.785,72.569 15.019,72.253 15.222,71.915 15.39,71.56 15.522,71.189 15.618,70.807 15.676,70.418 15.695,70.025 15.676,69.632 15.618,69.243 15.522,68.861 15.39,68.49 15.222,68.135 15.019,67.797 14.785,67.481 14.52,67.19 14.229,66.925 13.913,66.691 13.575,66.488 13.22,66.32 12.849,66.188 12.467,66.092 12.078,66.034 11.685,66.015 11.292,66.034 10.903,66.092 10.521,66.188 10.15,66.32 9.795,66.488 9.457,66.691 9.141,66.925 8.849,67.19 8.585,67.481 8.351,67.797 8.148,68.135 7.98,68.49 7.848,68.861 7.752,69.243 7.694,69.632 7.675,70.025 7.694,70.418 7.752,70.807 7.848,71.189 7.98,71.56 8.148,71.915 8.351,72.253 8.585,72.569 8.849,72.86 9.141,73.125 9.457,73.359 9.795,73.562 10.15,73.73 10.521,73.862 10.903,73.958 11.292,74.016 11.685,74.035
In6.Cu:
  region: 109.88,45.034 109.88,34.519 113.69,34.519 113.69,45.034
  region: 9.078,9.016 9.467,8.958 9.849,8.862 10.22,8.73 10.575,8.562 10.913,8.359 11.229,8.125 11.52,7.86 11.785,7.569 12.019,7.253 12.222,6.915 12.39,6.56 12.522,6.189 12.618,5.807 12.676,5.418 12.695,5.025 12.676,4.632 12.618,4.243 12.522,3.861 12.39,3.49 12.222,3.135 12.019,2.797 11.785,2.481 11.52,2.19 11.229,1.925 10.913,1.691 10.575,1.488 10.22,1.32 9.849,1.188 9.467,1.092 9.078,1.034 8.685,1.015 8.292,1.034 7.903,1.092 7.521,1.188 7.15,1.32 6.795,1.488 6.457,1.691 6.141,1.925 5.85,2.19 5.585,2.481 5.351,2.797 5.148,3.135 4.98,3.49 4.848,3.861 4.752,4.243 4.694,4.632 4.675,5.025 4.694,5.418 4.752,5.807 4.848,6.189 4.98,6.56 5.148,6.915 5.351,7.253 5.585,7.569 5.85,7.86 6.141,8.125 6.457,8.359 6.795,8.562 7.15,8.73 7.521,8.862 7.903,8.958 8.292,9.016 8.685,9.035
  region: 109.078,9.016 109.467,8.958 109.849,8.862 110.22,8.73 110.575,8.562 110.913,8.359 111.229,8.125 111.52,7.86 111.785,7.569 112.019,7.253 112.222,6.915 112.39,6.56 112.522,6.189 112.618,5.807 112.676,5.418 112.695,5.025 112.676,4.632 112.618,4.243 112.522,3.861 112.39,3.49 112.222,3.135 112.019,2.797 111.785,2.481 111.52,2.19 111.229,1.925 110.913,1.691 110.575,1.488 110.22,1.32 109.849,1.188 109.467,1.092 109.078,1.034 108.685,1.015 108.292,1.034 107.903,1.092 107.521,1.188 107.15,1.32 106.795,1.488 106.457,1.691 106.141,1.925 105.849,2.19 105.585,2.481 105.351,2.797 105.148,3.135 104.98,3.49 104.848,3.861 104.752,4.243 104.694,4.632 104.675,5.025 104.694,5.418 104.752,5.807 104.848,6.189 104.98,6.56 105.148,6.915 105.351,7.253 105.585,7.569 105.849,7.86 106.141,8.125 106.457,8.359 106.795,8.562 107.15,8.73 107.521,8.862 107.903,8.958 108.292,9.016 108.685,9.035
  region: 109.078,74.016 109.467,73.958 109.849,73.862 110.22,73.73 110.575,73.562 110.913,73.359 111.229,73.125 111.52,72.86 111.785,72.569 112.019,72.253 112.222,71.915 112.39,71.56 112.522,71.189 112.618,70.807 112.676,70.418 112.695,70.025 112.676,69.632 112.618,69.243 112.522,68.861 112.39,68.49 112.222,68.135 112.019,67.797 111.785,67.481 111.52,67.19 111.229,66.925 110.913,66.691 110.575,66.488 110.22,66.32 109.849,66.188 109.467,66.092 109.078,66.034 108.685,66.015 108.292,66.034 107.903,66.092 107.521,66.188 107.15,66.32 106.795,66.488 106.457,66.691 106.141,66.925 105.849,67.19 105.585,67.481 105.351,67.797 105.148,68.135 104.98,68.49 104.848,68.861 104.752,69.243 104.694,69.632 104.675,70.025 104.694,70.418 104.752,70.807 104.848,71.189 104.98,71.56 105.148,71.915 105.351,72.253 105.585,72.569 105.849,72.86 106.141,73.125 106.457,73.359 106.795,73.562 107.15,73.73 107.521,73.862 107.903,73.958 108.292,74.016 108.685,74.035
  region: 12.078,74.016 12.467,73.958 12.849,73.862 13.22,73.73 13.575,73.562 13.913,73.359 14.229,73.125 14.52,72.86 14.785,72.569 15.019,72.253 15.222,71.915 15.39,71.56 15.522,71.189 15.618,70.807 15.676,70.418 15.695,70.025 15.676,69.632 15.618,69.243 15.522,68.861 15.39,68.49 15.222,68.135 15.019,67.797 14.785,67.481 14.52,67.19 14.229,66.925 13.913,66.691 13.575,66.488 13.22,66.32 12.849,66.188 12.467,66.092 12.078,66.034 11.685,66.015 11.292,66.034 10.903,66.092 10.521,66.188 10.15,66.32 9.795,66.488 9.457,66.691 9.141,66.925 8.849,67.19 8.585,67.481 8.351,67.797 8.148,68.135 7.98,68.49 7.848,68.861 7.752,69.243 7.694,69.632 7.675,70.025 7.694,70.418 7.752,70.807 7.848,71.189 7.98,71.56 8.148,71.915 8.351,72.253 8.585,72.569 8.849,72.86 9.141,73.125 9.457,73.359 9.795,73.562 10.15,73.73 10.521,73.862 10.903,73.958 11.292,74.016 11.685,74.035
B.Cu:
  region: 109.88,45.034 109.88,34.519 113.69,34.519 113.69,45.034
  region: 9.078,9.016 9.467,8.958 9.849,8.862 10.22,8.73 10.575,8.562 10.913,8.359 11.229,8.125 11.52,7.86 11.785,7.569 12.019,7.253 12.222,6.915 12.39,6.56 12.522,6.189 12.618,5.807 12.676,5.418 12.695,5.025 12.676,4.632 12.618,4.243 12.522,3.861 12.39,3.49 12.222,3.135 12.019,2.797 11.785,2.481 11.52,2.19 11.229,1.925 10.913,1.691 10.575,1.488 10.22,1.32 9.849,1.188 9.467,1.092 9.078,1.034 8.685,1.015 8.292,1.034 7.903,1.092 7.521,1.188 7.15,1.32 6.795,1.488 6.457,1.691 6.141,1.925 5.85,2.19 5.585,2.481 5.351,2.797 5.148,3.135 4.98,3.49 4.848,3.861 4.752,4.243 4.694,4.632 4.675,5.025 4.694,5.418 4.752,5.807 4.848,6.189 4.98,6.56 5.148,6.915 5.351,7.253 5.585,7.569 5.85,7.86 6.141,8.125 6.457,8.359 6.795,8.562 7.15,8.73 7.521,8.862 7.903,8.958 8.292,9.016 8.685,9.035
  region: 109.078,9.016 109.467,8.958 109.849,8.862 110.22,8.73 110.575,8.562 110.913,8.359 111.229,8.125 111.52,7.86 111.785,7.569 112.019,7.253 112.222,6.915 112.39,6.56 112.522,6.189 112.618,5.807 112.676,5.418 112.695,5.025 112.676,4.632 112.618,4.243 112.522,3.861 112.39,3.49 112.222,3.135 112.019,2.797 111.785,2.481 111.52,2.19 111.229,1.925 110.913,1.691 110.575,1.488 110.22,1.32 109.849,1.188 109.467,1.092 109.078,1.034 108.685,1.015 108.292,1.034 107.903,1.092 107.521,1.188 107.15,1.32 106.795,1.488 106.457,1.691 106.141,1.925 105.849,2.19 105.585,2.481 105.351,2.797 105.148,3.135 104.98,3.49 104.848,3.861 104.752,4.243 104.694,4.632 104.675,5.025 104.694,5.418 104.752,5.807 104.848,6.189 104.98,6.56 105.148,6.915 105.351,7.253 105.585,7.569 105.849,7.86 106.141,8.125 106.457,8.359 106.795,8.562 107.15,8.73 107.521,8.862 107.903,8.958 108.292,9.016 108.685,9.035
  region: 109.078,74.016 109.467,73.958 109.849,73.862 110.22,73.73 110.575,73.562 110.913,73.359 111.229,73.125 111.52,72.86 111.785,72.569 112.019,72.253 112.222,71.915 112.39,71.56 112.522,71.189 112.618,70.807 112.676,70.418 112.695,70.025 112.676,69.632 112.618,69.243 112.522,68.861 112.39,68.49 112.222,68.135 112.019,67.797 111.785,67.481 111.52,67.19 111.229,66.925 110.913,66.691 110.575,66.488 110.22,66.32 109.849,66.188 109.467,66.092 109.078,66.034 108.685,66.015 108.292,66.034 107.903,66.092 107.521,66.188 107.15,66.32 106.795,66.488 106.457,66.691 106.141,66.925 105.849,67.19 105.585,67.481 105.351,67.797 105.148,68.135 104.98,68.49 104.848,68.861 104.752,69.243 104.694,69.632 104.675,70.025 104.694,70.418 104.752,70.807 104.848,71.189 104.98,71.56 105.148,71.915 105.351,72.253 105.585,72.569 105.849,72.86 106.141,73.125 106.457,73.359 106.795,73.562 107.15,73.73 107.521,73.862 107.903,73.958 108.292,74.016 108.685,74.035
  region: 12.078,74.016 12.467,73.958 12.849,73.862 13.22,73.73 13.575,73.562 13.913,73.359 14.229,73.125 14.52,72.86 14.785,72.569 15.019,72.253 15.222,71.915 15.39,71.56 15.522,71.189 15.618,70.807 15.676,70.418 15.695,70.025 15.676,69.632 15.618,69.243 15.522,68.861 15.39,68.49 15.222,68.135 15.019,67.797 14.785,67.481 14.52,67.19 14.229,66.925 13.913,66.691 13.575,66.488 13.22,66.32 12.849,66.188 12.467,66.092 12.078,66.034 11.685,66.015 11.292,66.034 10.903,66.092 10.521,66.188 10.15,66.32 9.795,66.488 9.457,66.691 9.141,66.925 8.849,67.19 8.585,67.481 8.351,67.797 8.148,68.135 7.98,68.49 7.848,68.861 7.752,69.243 7.694,69.632 7.675,70.025 7.694,70.418 7.752,70.807 7.848,71.189 7.98,71.56 8.148,71.915 8.351,72.253 8.585,72.569 8.849,72.86 9.141,73.125 9.457,73.359 9.795,73.562 10.15,73.73 10.521,73.862 10.903,73.958 11.292,74.016 11.685,74.035
Edge.Cuts:
  lines w0: 3.685,3.025 ccw(c6.686,3.026) 6.685,0.025 110.685,0.025 ccw(c110.684,3.026) 113.685,3.025 113.685,72.025 ccw(c110.684,72.024) 110.685,75.025 6.685,75.025 ccw(c6.686,72.024) 3.685,72.025 3.685,3.025
  lines w0.254: 3.685,3.025 ccw(c6.686,3.026) 6.685,0.025 110.685,0.025 ccw(c110.684,3.026) 113.685,3.025 113.685,72.025 ccw(c110.684,72.024) 110.685,75.025 6.685,75.025 ccw(c6.686,72.024) 3.685,72.025 3.685,3.025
